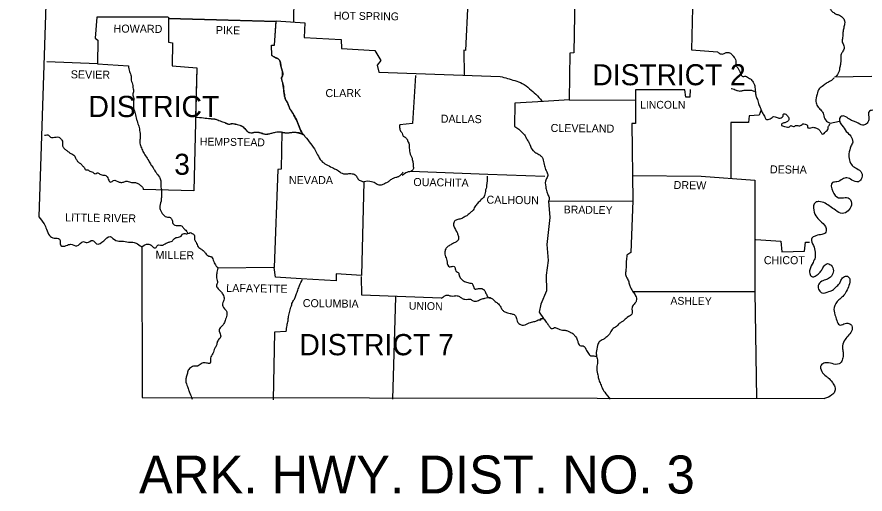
# Model space of a CAD drawing. Extents: x 79818 to 83933, y 50884 to 53307.
# Drawn here: x 83215.9 to 83671.4, y 52496.2 to 52752.3 of the extents above; entities that cross this region are included whole.
import ezdxf

# ---------------------------------------------------------------- set-up
doc = ezdxf.new("R2010")
doc.units = 0
doc.layers.add('Default', color=7, linetype='Continuous')
doc.layers.add('R_Draft', color=7, linetype='Continuous')

msp = doc.modelspace()

# ---------------------------------------------------------------- linework, layer by layer
at = {"layer": 'Default'}
for p, q in [((83365.57, 52812.38), (83364.41, 52749.58)), ((83355.16, 52749.97), (83297.27, 52751.49)), ((83655.07, 52720.18), (83675.07, 52720.48))]:
    msp.add_line(p, q, dxfattribs=at)
for points in [[(83215.87, 53082.48), (83236.57, 52916.28), (83227.57, 52644.98)], [(83515.68, 52773.68), (83515.07, 52733.08), (83512.77, 52732.98), (83512.47, 52707.88)], [(83579.07, 52772.38), (83578.27, 52734.68), (83592.17, 52733.58)], [(83458.07, 52760.48), (83456.87, 52734.28), (83455.97, 52734.58), (83456.07, 52720.98)], [(83297.17, 52752.18), (83258.77, 52752.28), (83257.87, 52740.88), (83259.27, 52739.88), (83259.17, 52727.08), (83231.87, 52728.28)], [(83297.27, 52752.18), (83297.27, 52738.88), (83299.47, 52738.48), (83299.27, 52726.08), (83312.47, 52725.08), (83310.87, 52658.98), (83283.67, 52659.68)], [(83297.27, 52751.49), (83355.2, 52749.97)], [(83297.27, 52751.49), (83297.27, 52738.88), (83299.47, 52738.48), (83299.27, 52726.08), (83312.47, 52725.08), (83311.83, 52698.52)], [(83352.77, 52731.68), (83352.57, 52737.18), (83354.17, 52737.28), (83355.17, 52750.18), (83370.57, 52749.18), (83370.17, 52741.28), (83390.07, 52740.18), (83390.17, 52735.38), (83408.17, 52734.28), (83411.27, 52728.88), (83409.37, 52726.48), (83410.27, 52722.78), (83475.47, 52720.38)], [(83352.77, 52731.68), (83352.57, 52737.18), (83354.17, 52737.28), (83355.16, 52749.97)], [(83259.17, 52727.08), (83275.77, 52726.08)], [(83429.87, 52720.88), (83428.37, 52695.18), (83421.47, 52694.38)], [(83577.54, 52713.35), (83577.37, 52709.28), (83575.07, 52709.28), (83574.67, 52713.18), (83548.07, 52713.18), (83548.1, 52707.68)], [(83498.64, 52707.03), (83483.27, 52706.08), (83483.17, 52693.58)], [(83512.47, 52707.88), (83498.64, 52707.03)], [(83512.47, 52707.88), (83547.87, 52707.68)], [(83548.1, 52707.68), (83548.17, 52695.18), (83546.07, 52695.08), (83546.67, 52653.58)], [(83615.67, 52702.38), (83614.47, 52699.68), (83609.17, 52699.18), (83608.87, 52695.58), (83599.37, 52695.58), (83599.27, 52665.68)], [(83358.07, 52690.58), (83357.87, 52670.68), (83356.07, 52670.48), (83354.07, 52617.78)], [(83427.37, 52669.48), (83468.77, 52667.98), (83499.47, 52666.78)], [(83546.37, 52667.18), (83583.47, 52666.88), (83612.27, 52664.68)], [(83402.17, 52663.88), (83400.87, 52613.48), (83387.37, 52614.38), (83387.27, 52610.68), (83368.6, 52611.77)], [(83612.27, 52664.68), (83612.27, 52604.88), (83613.07, 52547.38)], [(83501.47, 52653.48), (83502.04, 52644.58), (83500.57, 52630.1), (83501.2, 52621.5), (83500.15, 52613.73), (83500.36, 52605.34), (83497.22, 52598.2), (83496.38, 52593.8), (83498.68, 52590.44)], [(83501.47, 52653.48), (83546.67, 52653.58)], [(83546.67, 52653.58), (83545.67, 52625.78), (83543.47, 52624.38)], [(83612.77, 52632.78), (83626.17, 52631.98), (83626.77, 52626.18), (83638.87, 52626.58), (83639.37, 52631.48), (83641.67, 52631.48)], [(83282.87, 52628.88), (83283.07, 52547.98), (83649.57, 52547.38)], [(83354.07, 52617.78), (83323.77, 52617.48)], [(83368.6, 52611.77), (83354.77, 52612.58), (83354.07, 52617.78)], [(83443.77, 52601.28), (83401.07, 52602.88), (83400.87, 52612.98)], [(83419.27, 52601.98), (83417.67, 52547.08)], [(83547.27, 52604.98), (83612.27, 52604.98)], [(83360.47, 52583.48), (83354.27, 52583.08), (83353.57, 52546.78)]]:
    msp.add_lwpolyline(points, dxfattribs=at)
for points in [[(83733.77, 52817.48), (83731.47, 52814.58), (83728.07, 52816.38), (83728.07, 52818.78), (83728.57, 52821.28), (83727.37, 52822.88), (83725.27, 52822.18), (83725.27, 52819.08), (83725.07, 52816.08), (83724.47, 52811.78), (83725.87, 52810.48), (83729.07, 52810.08), (83731.37, 52809.48), (83732.77, 52807.18), (83732.67, 52804.38), (83731.57, 52801.68), (83729.97, 52799.48), (83727.47, 52798.68), (83725.47, 52799.98), (83724.67, 52802.58), (83723.77, 52804.88), (83722.07, 52806.58), (83720.27, 52804.68), (83719.87, 52801.18), (83719.97, 52798.18), (83719.97, 52794.08), (83722.57, 52791.38), (83724.17, 52788.28), (83723.67, 52785.48), (83721.77, 52782.18), (83720.97, 52779.28), (83720.17, 52775.38), (83720.27, 52771.08), (83719.57, 52766.88), (83718.17, 52764.08), (83715.57, 52761.78), (83713.87, 52760.28), (83712.47, 52758.78), (83711.77, 52755.78), (83711.27, 52753.68), (83709.37, 52751.18), (83707.87, 52750.98), (83706.67, 52751.98), (83706.27, 52753.68), (83706.27, 52755.38), (83705.47, 52757.08), (83702.97, 52757.78), (83700.97, 52757.68), (83700.07, 52756.28), (83701.37, 52752.38), (83701.87, 52749.88), (83701.17, 52746.48), (83701.57, 52746.08), (83697.97, 52744.18), (83695.07, 52743.88), (83692.67, 52743.18), (83690.37, 52741.68), (83689.27, 52739.48), (83687.67, 52737.68), (83686.27, 52735.98), (83684.37, 52735.18), (83682.27, 52735.58), (83679.47, 52735.88), (83677.87, 52733.88), (83678.37, 52730.98), (83680.27, 52729.28), (83683.07, 52728.48), (83685.97, 52728.68), (83688.77, 52728.98), (83691.37, 52727.58), (83690.87, 52724.88), (83688.37, 52723.58), (83684.67, 52723.18), (83681.67, 52723.48), (83678.07, 52722.68), (83676.27, 52720.38), (83677.27, 52716.88), (83681.17, 52715.48), (83682.97, 52712.18), (83683.07, 52709.08), (83681.77, 52704.98), (83679.97, 52703.08), (83676.47, 52702.28), (83673.77, 52701.78), (83673.37, 52697.18), (83672.17, 52694.88), (83670.07, 52694.18), (83667.07, 52695.68), (83665.27, 52696.38), (83663.07, 52697.38), (83660.27, 52699.08), (83658.17, 52698.78), (83658.77, 52694.38), (83658.97, 52694.18), (83661.37, 52690.88), (83663.77, 52688.28), (83664.87, 52685.18)], [(83630.17, 52785.28), (83630.47, 52781.18), (83632.87, 52780.58), (83633.87, 52779.48), (83634.37, 52777.18), (83636.07, 52776.18), (83638.37, 52774.78), (83639.77, 52773.78), (83640.77, 52772.18), (83641.37, 52769.58), (83642.97, 52767.88), (83645.17, 52767.08), (83646.77, 52765.18), (83647.77, 52762.48), (83649.37, 52761.28), (83650.97, 52759.18), (83651.77, 52758.28), (83653.17, 52755.88), (83654.57, 52754.68), (83655.57, 52753.98), (83657.17, 52753.48), (83659.17, 52752.18), (83660.47, 52750.18), (83660.47, 52748.68), (83659.97, 52746.38), (83659.57, 52743.98), (83659.37, 52741.28), (83659.17, 52738.88), (83660.07, 52736.88), (83659.57, 52733.88), (83658.57, 52732.28), (83658.47, 52730.08), (83658.17, 52726.78), (83657.77, 52724.88), (83656.87, 52721.78), (83655.57, 52720.18)], [(83352.77, 52731.68), (83354.37, 52730.68), (83356.27, 52729.78), (83357.27, 52728.28), (83357.67, 52725.98), (83358.37, 52723.48), (83358.57, 52720.88), (83357.97, 52719.48), (83358.77, 52716.28), (83359.07, 52714.08), (83359.37, 52711.48), (83360.17, 52707.98), (83361.47, 52705.58), (83362.67, 52702.68), (83364.67, 52699.58), (83366.37, 52696.18), (83367.17, 52694.38), (83368.67, 52690.68), (83370.57, 52688.18), (83373.57, 52684.38), (83376.27, 52680.48), (83377.77, 52677.58), (83380.07, 52674.38), (83382.67, 52672.78), (83385.97, 52671.08), (83388.07, 52670.08), (83390.47, 52668.38), (83393.57, 52668.18), (83395.87, 52668.18), (83397.97, 52667.28), (83398.97, 52665.48), (83400.77, 52664.28), (83402.17, 52663.88)], [(83369.74, 52689.22), (83368.67, 52690.68), (83368.22, 52691.57), (83367.86, 52692.5), (83367.53, 52693.45), (83367.17, 52694.38), (83366.37, 52696.18), (83364.67, 52699.58), (83364.2, 52700.37), (83363.67, 52701.13), (83363.15, 52701.89), (83362.67, 52702.68), (83362.34, 52703.39), (83362.06, 52704.13), (83361.78, 52704.86), (83361.47, 52705.58), (83361.16, 52706.18), (83360.8, 52706.77), (83360.46, 52707.36), (83360.17, 52707.98), (83359.89, 52708.84), (83359.67, 52709.71), (83359.37, 52711.48), (83359.07, 52714.08), (83358.77, 52716.28), (83358.6, 52717.09), (83358.37, 52717.89), (83358.14, 52718.69), (83357.97, 52719.48), (83358.04, 52719.84), (83358.24, 52720.18), (83358.46, 52720.53), (83358.57, 52720.88), (83358.58, 52721.52), (83358.56, 52722.18), (83358.5, 52722.84), (83358.37, 52723.48), (83358.21, 52724.11), (83358.02, 52724.73), (83357.84, 52725.36), (83357.67, 52725.98), (83357.56, 52726.55), (83357.48, 52727.13), (83357.39, 52727.71), (83357.27, 52728.28), (83356.91, 52729.12), (83356.27, 52729.78), (83355.81, 52730.05), (83355.32, 52730.25), (83354.84, 52730.45), (83354.37, 52730.68), (83352.77, 52731.68)], [(83592.17, 52733.58), (83593.67, 52732.58), (83595.77, 52732.68), (83597.17, 52733.28), (83598.27, 52733.18), (83599.77, 52732.28), (83600.77, 52731.08), (83601.47, 52730.18), (83601.97, 52728.78), (83601.97, 52727.48), (83602.47, 52725.68), (83603.07, 52724.98), (83603.87, 52723.68), (83604.37, 52722.48), (83604.67, 52721.68), (83605.77, 52720.38), (83606.77, 52720.48), (83607.67, 52720.38), (83608.87, 52719.68), (83610.67, 52718.28), (83610.97, 52717.88), (83612.17, 52715.28), (83612.37, 52713.68), (83612.57, 52711.58), (83612.97, 52709.58), (83613.77, 52707.38), (83614.17, 52705.88), (83615.07, 52703.78), (83615.67, 52702.38), (83616.47, 52700.58), (83617.67, 52698.58), (83618.17, 52697.38), (83619.87, 52697.48), (83621.07, 52697.98), (83621.97, 52698.78), (83623.07, 52698.68), (83624.27, 52698.28), (83625.87, 52697.98), (83626.87, 52698.58), (83627.37, 52698.98), (83627.47, 52699.88), (83628.37, 52700.38), (83629.37, 52699.68), (83630.47, 52698.08), (83630.47, 52697.08), (83630.07, 52696.48), (83628.77, 52695.68), (83626.97, 52695.08), (83626.47, 52694.38), (83628.17, 52693.58), (83630.87, 52693.38), (83631.57, 52693.98), (83633.37, 52693.48), (83634.07, 52693.98), (83636.47, 52693.88), (83637.57, 52694.68), (83639.77, 52694.58), (83640.47, 52694.08), (83640.47, 52693.18), (83642.27, 52692.78), (83643.57, 52693.08), (83645.27, 52692.58), (83646.77, 52691.78), (83647.57, 52690.68), (83648.57, 52689.48), (83649.47, 52689.78), (83650.17, 52690.68), (83651.67, 52692.28), (83651.67, 52693.28), (83652.07, 52693.98), (83652.57, 52694.98)], [(83275.77, 52726.08), (83276.27, 52723.08), (83277.17, 52720.48), (83277.27, 52718.48), (83278.17, 52715.48), (83278.17, 52714.38), (83278.47, 52712.18), (83278.07, 52710.98), (83278.57, 52708.58), (83278.47, 52706.78), (83278.47, 52705.28), (83278.57, 52702.78), (83279.37, 52700.58), (83280.17, 52697.28), (83280.67, 52695.58), (83281.47, 52692.98), (83281.97, 52689.78), (83282.07, 52687.38), (83281.87, 52685.18), (83282.47, 52682.68), (83283.57, 52680.18), (83284.97, 52677.78), (83286.67, 52675.08), (83287.87, 52672.98), (83289.37, 52670.68), (83290.57, 52668.78), (83292.37, 52666.38), (83293.17, 52664.38), (83293.17, 52661.58), (83293.57, 52658.98), (83293.47, 52656.08), (83293.27, 52653.48), (83292.57, 52649.88), (83293.07, 52648.18), (83294.97, 52645.68), (83296.17, 52644.98), (83298.27, 52644.58), (83299.27, 52643.18), (83299.87, 52641.08), (83301.97, 52640.38), (83304.27, 52640.18), (83305.37, 52638.98), (83306.87, 52637.38), (83307.74, 52636)], [(83475.47, 52720.38), (83483.27, 52718.18), (83487.27, 52716.68), (83491.27, 52713.78), (83494.57, 52710.88), (83497.87, 52707.18)], [(83654.87, 52719.58), (83652.77, 52717.88), (83650.97, 52716.88), (83649.07, 52715.48), (83646.77, 52713.78), (83645.67, 52710.88), (83645.07, 52706.88), (83645.87, 52704.48), (83647.67, 52702.38), (83648.87, 52700.68), (83649.77, 52697.68), (83651.97, 52695.58), (83652.67, 52695.28)], [(83599.58, 52713.89), (83599.77, 52713.88), (83601.07, 52713.58), (83602.17, 52712.98), (83602.97, 52712.78), (83604.17, 52712.58), (83605.17, 52712.68), (83606.87, 52713.08), (83607.87, 52713.08), (83609.47, 52713.08), (83610.47, 52712.98), (83611.97, 52712.18)], [(83311.75, 52698.52), (83316.07, 52698.18), (83319.57, 52697.78), (83322.27, 52697.48), (83325.07, 52696.48), (83327.57, 52695.58), (83329.17, 52694.88), (83331.87, 52695.08), (83334.17, 52694.58), (83336.77, 52693.68), (83338.67, 52691.98), (83339.87, 52690.68), (83342.17, 52690.18), (83344.07, 52690.48), (83346.37, 52690.28), (83348.97, 52689.48), (83351.07, 52689.58), (83352.77, 52689.98), (83354.77, 52690.48), (83357.27, 52690.68), (83359.17, 52690.28), (83361.67, 52690.18), (83364.57, 52690.48), (83370.17, 52688.93)], [(83311.83, 52698.52), (83316.07, 52698.18), (83319.57, 52697.78), (83320.93, 52697.67), (83321.61, 52697.61), (83321.94, 52697.55), (83322.27, 52697.48), (83322.99, 52697.27), (83323.69, 52697.02), (83325.07, 52696.48), (83327.57, 52695.58), (83327.98, 52695.42), (83328.37, 52695.23), (83328.77, 52695.04), (83329.17, 52694.88), (83329.84, 52694.81), (83330.52, 52694.93), (83331.2, 52695.07), (83331.87, 52695.08), (83333.03, 52694.86), (83334.17, 52694.58), (83335.51, 52694.23), (83336.15, 52694), (83336.47, 52693.85), (83336.77, 52693.68), (83337.78, 52692.88), (83338.67, 52691.98), (83338.96, 52691.66), (83339.23, 52691.32), (83339.87, 52690.68), (83340.43, 52690.38), (83341.01, 52690.23), (83342.17, 52690.18), (83342.65, 52690.24), (83343.12, 52690.34), (83343.6, 52690.44), (83344.07, 52690.48), (83346.37, 52690.28), (83347.03, 52690.11), (83347.68, 52689.86), (83348.32, 52689.63), (83348.97, 52689.48), (83349.5, 52689.44), (83350.03, 52689.44), (83351.07, 52689.58), (83352.77, 52689.98), (83354.77, 52690.48), (83356.02, 52690.68), (83356.65, 52690.7), (83357.27, 52690.68), (83357.75, 52690.61), (83358.22, 52690.49), (83358.7, 52690.37), (83359.17, 52690.28), (83360.42, 52690.2), (83361.67, 52690.18), (83362.4, 52690.23), (83363.13, 52690.32), (83363.85, 52690.42), (83364.57, 52690.48), (83365.9, 52690.45), (83367.21, 52690.26), (83369.74, 52689.22)], [(83421.47, 52694.38), (83421.47, 52692.48), (83422.17, 52690.68), (83422.87, 52689.88), (83423.17, 52688.58), (83424.07, 52687.98), (83425.37, 52686.78), (83426.07, 52685.08), (83426.57, 52683.98), (83426.57, 52682.58), (83426.67, 52681.18), (83426.87, 52679.48), (83428.07, 52676.48), (83428.37, 52675.28), (83428.57, 52674.28), (83428.67, 52672.58), (83428.67, 52670.58), (83427.37, 52669.48)], [(83483.17, 52693.58), (83485.47, 52692.08), (83487.37, 52690.08), (83488.77, 52688.58), (83489.67, 52686.88), (83490.87, 52684.88), (83492.57, 52681.08), (83494.07, 52679.78), (83496.17, 52678.48), (83497.47, 52677.58), (83498.77, 52674.68), (83499.37, 52671.78), (83500.47, 52669.18), (83500.97, 52667.18), (83500.07, 52665.18), (83499.87, 52661.18), (83500.47, 52658.48), (83501.27, 52656.48), (83501.77, 52654.18), (83501.47, 52653.48)], [(83230.67, 52688.78), (83232.87, 52688.88), (83234.37, 52687.58), (83235.27, 52687.68), (83236.87, 52687.88), (83238.37, 52687.78), (83239.47, 52686.88), (83240.37, 52685.28), (83240.27, 52683.78), (83240.37, 52683.18), (83241.07, 52681.88), (83242.27, 52680.88), (83243.57, 52679.88), (83244.77, 52679.08), (83246.77, 52677.78), (83246.97, 52677.38), (83247.77, 52675.78), (83248.77, 52674.48), (83249.97, 52673.68), (83251.27, 52672.28), (83251.87, 52671.68), (83252.87, 52670.28), (83253.97, 52670.18), (83255.47, 52669.28), (83256.57, 52668.98), (83257.77, 52668.18), (83258.97, 52668.58), (83260.47, 52667.98), (83262.47, 52667.38), (83263.57, 52667.18), (83264.87, 52665.28), (83266.17, 52663.68), (83267.77, 52664.58), (83270.77, 52663.68), (83272.67, 52663.58), (83274.37, 52664.08), (83275.67, 52663.98), (83278.07, 52663.38), (83279.57, 52663.38), (83281.17, 52662.78), (83282.67, 52661.58), (83283.67, 52660.28), (83283.67, 52659.68)], [(83664.87, 52685.18), (83663.87, 52682.88), (83662.77, 52678.88), (83663.07, 52675.48), (83664.57, 52672.58), (83666.97, 52670.98), (83669.57, 52668.68), (83669.37, 52665.18), (83667.87, 52663.88), (83664.37, 52664.78), (83661.67, 52665.98), (83659.37, 52665.28), (83656.27, 52663.78), (83653.97, 52663.48), (83654.07, 52658.68), (83657.17, 52655.28), (83659.87, 52655.28), (83662.97, 52654.88), (83664.07, 52651.28), (83662.27, 52648.28), (83659.27, 52646.78), (83655.47, 52648.58), (83652.77, 52650.48), (83650.07, 52652.28), (83646.67, 52653.18), (83644.77, 52652.78), (83643.87, 52648.58), (83645.47, 52644.78), (83648.07, 52642.18), (83650.47, 52638.78), (83650.07, 52636.28), (83648.27, 52635.58), (83645.07, 52634.88), (83643.17, 52633.88), (83642.67, 52633.08), (83643.67, 52629.68), (83644.57, 52625.98), (83644.57, 52623.18), (83643.47, 52620.58), (83641.77, 52616.58), (83641.97, 52613.98), (83643.17, 52612.78), (83644.67, 52613.18), (83646.67, 52614.58), (83647.97, 52616.18), (83649.07, 52618.18), (83651.17, 52619.88), (83653.77, 52618.38), (83654.37, 52615.28), (83652.87, 52612.58), (83650.77, 52611.38), (83648.17, 52610.38), (83646.27, 52608.18), (83646.77, 52605.58), (83648.27, 52604.18), (83651.97, 52604.88), (83654.47, 52605.98), (83655.87, 52607.38), (83657.57, 52609.08), (83658.47, 52610.78), (83659.77, 52612.58), (83662.07, 52613.08), (83663.17, 52611.58), (83662.77, 52608.18), (83661.37, 52604.98), (83659.47, 52602.28), (83657.37, 52600.38), (83654.77, 52596.28), (83655.27, 52592.48), (83656.27, 52589.38), (83657.67, 52586.98), (83660.07, 52587.48), (83662.77, 52587.78), (83664.37, 52586.48), (83664.17, 52583.68), (83662.17, 52580.98), (83660.27, 52578.38), (83659.27, 52574.78), (83659.67, 52572.28), (83659.67, 52569.98), (83658.87, 52567.48), (83657.47, 52566.08), (83653.77, 52566.18), (83649.87, 52566.58), (83647.77, 52565.38), (83648.17, 52561.98), (83650.47, 52559.48), (83652.07, 52558.18), (83654.37, 52555.38), (83655.37, 52553.08), (83655.07, 52551.08), (83653.67, 52549.38), (83649.57, 52547.38)], [(83423.27, 52668.98), (83422.17, 52667.68), (83420.87, 52666.58), (83419.37, 52666.08), (83417.97, 52665.68), (83416.17, 52664.48), (83414.77, 52663.48), (83412.87, 52662.58), (83411.07, 52661.98), (83408.87, 52662.68), (83407.67, 52663.38), (83406.37, 52663.88), (83402.17, 52663.88)], [(83422.87, 52667.38), (83425.47, 52669.08), (83428.37, 52669.48)], [(83468.37, 52666.78), (83468.17, 52661.78), (83467.47, 52658.68), (83466.77, 52655.88), (83465.27, 52654.28), (83463.67, 52652.68), (83462.17, 52650.88), (83460.87, 52648.68), (83459.57, 52647.28), (83457.87, 52645.88), (83456.17, 52644.88), (83454.27, 52643.98), (83452.17, 52643.48), (83450.67, 52642.38), (83450.57, 52639.98), (83452.27, 52636.58), (83452.87, 52634.98), (83453.07, 52633.08), (83452.37, 52631.98), (83450.77, 52631.08), (83448.87, 52629.98), (83447.17, 52628.98), (83445.97, 52627.28), (83445.77, 52624.98), (83446.57, 52622.28), (83446.87, 52620.68), (83448.17, 52618.18), (83449.17, 52618.28), (83450.97, 52618.18), (83451.17, 52617.68), (83451.27, 52617.18), (83451.67, 52615.88), (83453.17, 52614.78), (83453.37, 52613.78), (83454.27, 52611.88), (83455.77, 52610.58), (83456.87, 52610.18), (83459.17, 52609.48), (83460.37, 52609.18), (83461.67, 52606.28), (83463.27, 52606.38), (83464.47, 52606.58), (83466.47, 52606.08), (83467.37, 52604.88), (83468.27, 52602.88), (83469.47, 52601.48), (83470.27, 52601.48)], [(83227.57, 52644.98), (83230.47, 52641.18), (83231.67, 52638.48), (83233.37, 52634.98), (83235.87, 52633.58), (83238.77, 52633.08), (83239.37, 52629.68), (83242.37, 52629.58), (83244.77, 52630.28), (83248.07, 52629.38), (83251.57, 52631.78), (83253.57, 52631.18), (83256.47, 52632.38), (83258.67, 52630.58), (83262.47, 52632.18), (83265.87, 52634.38), (83269.07, 52632.28), (83272.17, 52631.98), (83275.87, 52631.48), (83278.77, 52631.28), (83281.37, 52629.98), (83283.27, 52628.68), (83282.87, 52628.88)], [(83282.87, 52628.88), (83286.37, 52630.38), (83287.87, 52629.88), (83289.17, 52628.58), (83290.67, 52628.58), (83291.47, 52629.78), (83292.97, 52629.88), (83294.17, 52629.78), (83295.47, 52630.58), (83296.57, 52631.08), (83298.07, 52631.58), (83299.17, 52631.98), (83300.17, 52633.08), (83301.97, 52633.98), (83304.07, 52634.68), (83304.67, 52635.68), (83305.67, 52636.08), (83307.67, 52635.98), (83308.97, 52636.58), (83310.07, 52636.08), (83311.07, 52635.38), (83311.27, 52632.78), (83312.07, 52631.38), (83313.27, 52628.88), (83314.97, 52627.58), (83316.57, 52626.28), (83317.17, 52625.48), (83318.87, 52623.98), (83320.37, 52623.48), (83321.07, 52622.38), (83322.17, 52619.78), (83323.77, 52617.48)], [(83543.47, 52624.38), (83543.17, 52621.28), (83543.07, 52618.38), (83542.87, 52615.58), (83542.87, 52613.48), (83544.07, 52611.18), (83544.77, 52608.98), (83545.47, 52607.08), (83546.87, 52604.58), (83548.17, 52602.68), (83548.57, 52599.98), (83547.77, 52598.58), (83546.27, 52596.48), (83546.17, 52592.68), (83544.37, 52591.48), (83542.07, 52589.48), (83540.77, 52588.58), (83539.37, 52587.68), (83537.87, 52586.08), (83535.67, 52584.58), (83534.07, 52582.08), (83532.27, 52580.18), (83530.77, 52579.18), (83528.67, 52577.88), (83527.77, 52575.88), (83527.07, 52572.18), (83527.37, 52569.48), (83527.77, 52567.08), (83527.27, 52564.08), (83527.77, 52560.78), (83528.27, 52558.18), (83529.07, 52555.88), (83530.17, 52553.28), (83531.57, 52550.88), (83534.57, 52547.18)], [(83323.77, 52617.48), (83323.17, 52614.58), (83323.07, 52612.28), (83323.57, 52609.58), (83323.07, 52608.28), (83323.87, 52606.38), (83325.37, 52604.88), (83326.47, 52603.28), (83327.17, 52600.98), (83326.27, 52598.38), (83327.27, 52595.68), (83328.17, 52594.68), (83328.67, 52593.08), (83327.97, 52589.98), (83327.07, 52587.68), (83325.07, 52585.38), (83324.47, 52584.28), (83324.77, 52582.78), (83325.27, 52580.38), (83324.77, 52579.68), (83323.47, 52577.98), (83323.07, 52576.08), (83322.17, 52574.48), (83321.17, 52571.58), (83319.87, 52569.18), (83319.67, 52566.48), (83317.67, 52566.48), (83315.37, 52566.48), (83313.27, 52564.98), (83311.37, 52564.88), (83309.07, 52563.98), (83307.67, 52562.08), (83307.17, 52559.98), (83306.57, 52557.98), (83307.17, 52554.58), (83308.07, 52552.18), (83308.77, 52550.28), (83309.97, 52547.18)], [(83360.47, 52583.48), (83360.97, 52586.68), (83361.47, 52589.18), (83361.77, 52591.58), (83362.37, 52594.28), (83363.27, 52597.18), (83364.07, 52599.58), (83365.17, 52601.28), (83365.87, 52603.28), (83366.77, 52605.68), (83367.67, 52608.18), (83369.27, 52611.38)], [(83443.77, 52601.28), (83445.37, 52602.38), (83446.87, 52602.98), (83448.37, 52602.68), (83449.97, 52602.48), (83451.37, 52602.68), (83453.17, 52602.38), (83454.67, 52601.48), (83456.37, 52600.78), (83458.07, 52600.78), (83459.57, 52600.78), (83460.87, 52599.88), (83463.27, 52599.98), (83465.27, 52600.78), (83467.27, 52601.38), (83469.97, 52601.68), (83472.37, 52599.98), (83474.07, 52598.58), (83475.47, 52596.98), (83476.47, 52595.18), (83477.57, 52594.18), (83479.37, 52593.48), (83480.77, 52593.18), (83482.47, 52592.68), (83483.37, 52592.28), (83484.17, 52590.38), (83485.47, 52587.78), (83487.97, 52586.88), (83491.07, 52588.08), (83493.57, 52588.78), (83495.37, 52589.38), (83496.47, 52589.78), (83497.47, 52589.88), (83497.17, 52590.08), (83498.37, 52590.38), (83499.47, 52589.58), (83500.17, 52588.48), (83501.37, 52586.88), (83502.47, 52585.48), (83503.57, 52584.98), (83504.67, 52585.58), (83506.17, 52585.08), (83507.47, 52584.58), (83508.97, 52584.18), (83510.27, 52584.08), (83511.97, 52583.68), (83513.27, 52582.98), (83514.47, 52582.28), (83515.67, 52580.98), (83516.87, 52578.98), (83517.27, 52577.38), (83518.67, 52575.78), (83519.97, 52575.78), (83521.87, 52573.18), (83522.57, 52572.18), (83524.07, 52570.38), (83525.17, 52570.38), (83527.27, 52569.98)]]:
    msp.add_spline(points, degree=3, dxfattribs=at)
at = {"layer": 'R_Draft'}
msp.add_line((83652.71, 52695.26), (83657.78, 52696.33), dxfattribs=at)

# ---------------------------------------------------------------- texts
at = {"layer": 'Default'}
for s, height, rotation, p in [('HOT SPRING', 4.201, 359.2216, (83386.07, 52750.98)), ('HOWARD', 4.301, 359.5145, (83267.77, 52743.98)), ('PIKE', 4.299, 359.0452, (83322.67, 52743.18)), ('SEVIER', 4.301, 359.4271, (83244.77, 52719.38)), ('DALLAS', 4.3, 359.2462, (83443.47, 52695.59)), ('CLEVELAND', 4.301, 359.3376, (83502.5, 52690.61)), ('HEMPSTEAD', 4.199, 359.1885, (83314.07, 52683.38)), ('DESHA', 4.299, 359.3704, (83620.31, 52668.38)), ('OUACHITA', 4.301, 359.2043, (83428.77, 52661.58)), ('DREW', 4.299, 359.2258, (83568.57, 52659.98)), ('CALHOUN', 4.301, 359.3634, (83468.07, 52652.08)), ('BRADLEY', 4.199, 359.1449, (83509.57, 52646.88)), ('LITTLE RIVER', 4.3007, 359.1697, (83241.77, 52642.58)), ('MILLER', 4.3, 359.1319, (83290.27, 52622.48)), ('LAFAYETTE', 4.299, 359.1839, (83328.27, 52604.68)), ('ASHLEY', 4.201, 359.2361, (83566.87, 52597.88)), ('COLUMBIA', 4.3, 359.2125, (83369.37, 52596.58)), ('UNION', 4.201, 358.9584, (83426.37, 52595.18))]:
    msp.add_text(s, height=height, rotation=rotation, dxfattribs=at).set_placement(p)
for s, height, p in [('DISTRICT 2', 11.3, (83525.02, 52715.67)), ('CLARK', 4.3, (83381.6, 52709.31)), ('DISTRICT', 11.4, (83254.27, 52698.58)), ('LINCOLN', 4.2, (83550.57, 52703.08)), ('3', 11.3, (83300.37, 52667.58)), ('NEVADA', 4.3, (83361.97, 52662.58)), ('CHICOT', 4.3, (83617.07, 52619.58)), ('DISTRICT 7', 11.4, (83367.57, 52570.68)), ('  ARK. HWY. DIST. NO. 3', 20.4, (83266.24, 52496.46))]:
    msp.add_text(s, height=height, dxfattribs=at).set_placement(p)

doc.saveas('drawing.dxf')
